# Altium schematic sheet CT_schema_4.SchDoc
size 283 x 147 mm
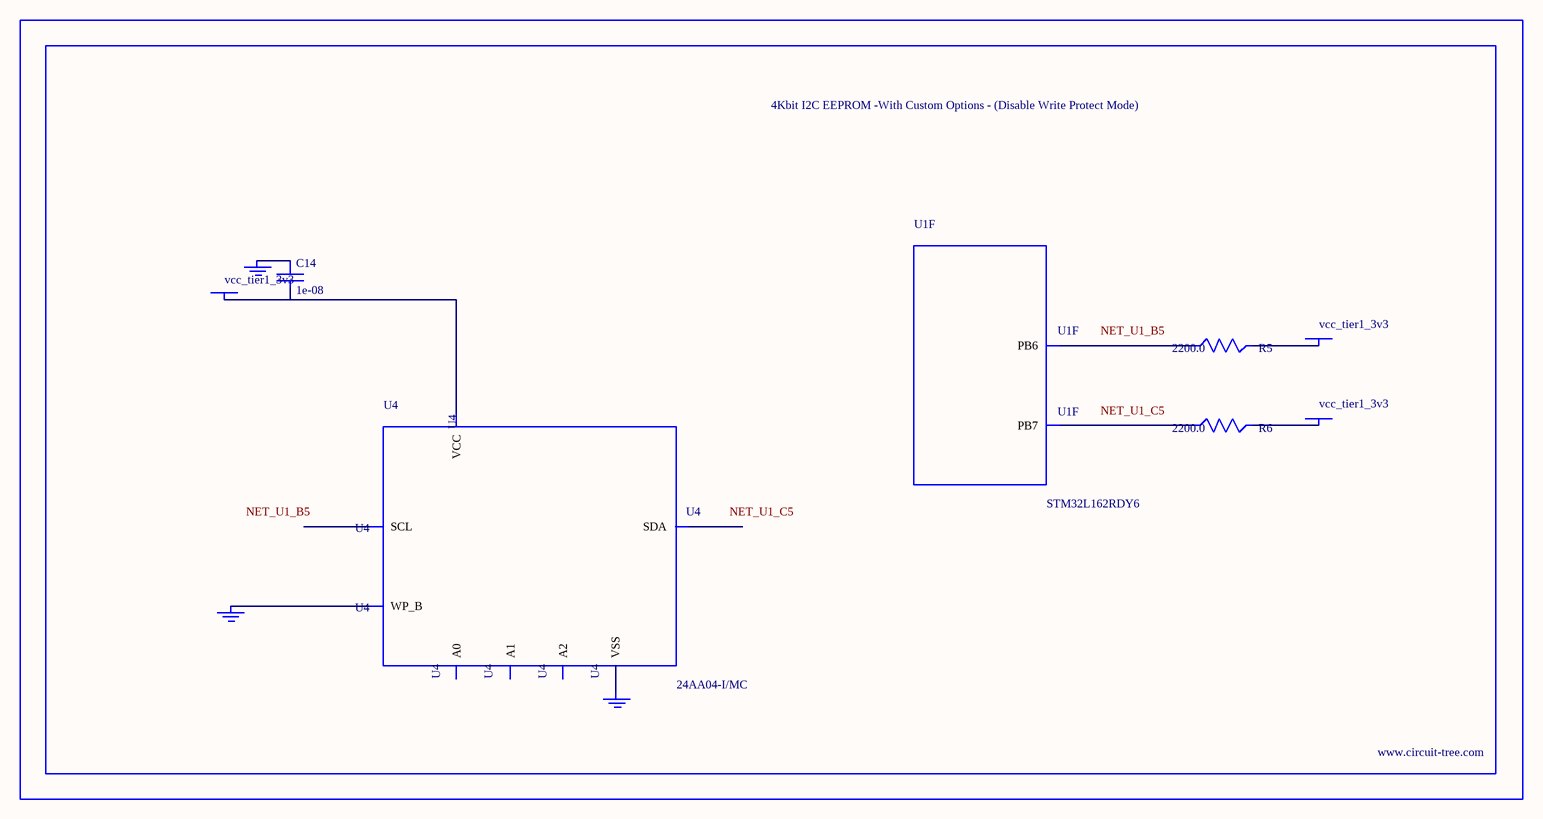
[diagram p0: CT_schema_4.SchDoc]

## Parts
BORDER3  (no value)
C14  1e-08  [C0402]
GND_INSTANCE_3_0  (no value)
GND_INSTANCE_3_1  (no value)
GND_INSTANCE_3_2  (no value)
POWER_INSTANCE_3_0  vcc_tier1_3v3
POWER_INSTANCE_3_1  vcc_tier1_3v3
POWER_INSTANCE_3_2  vcc_tier1_3v3
R5  2200.0  [R0603]
R6  2200.0  [R0603]
U1  STM32L162RDY6  [WLCSP64]  (part F of 6)
U4  24AA04-I/MC  [TDFN-8/6MM]

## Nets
NetC14_1: C14.1 GND_INSTANCE_3_1.0(GND)
NetC14_2: C14.2 POWER_INSTANCE_3_0.0(PWR) U4.8(VCC)
NetGND_INSTANCE_3_0_0: GND_INSTANCE_3_0.0(GND) U4.7(WP_B)
NetGND_INSTANCE_3_2_0: GND_INSTANCE_3_2.0(GND) U4.4(VSS)
NetPOWER_INSTANCE_3_1_0: POWER_INSTANCE_3_1.0(PWR) R5.2
NetPOWER_INSTANCE_3_2_0: POWER_INSTANCE_3_2.0(PWR) R6.2
NetR5_1: R5.1 U1.B5(PB6)
NetR6_1: R6.1 U1.C5(PB7)

Not connected (* = marked no-connect by the designer): U4 1(A0) 2(A1) 3(A2) 5(SDA) 6(SCL)

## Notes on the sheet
- Labels drawn without touching a wire or pin: NET_U1_B5, NET_U1_C5

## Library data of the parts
BORDER3 = BORDER_PAGE3
C14 = C0402C103K3RAC
GND_INSTANCE_3_0-GND_INSTANCE_3_2 = GND
POWER_INSTANCE_3_0-POWER_INSTANCE_3_2 = PWR
R5 R6 = RC0603JR-072K2L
